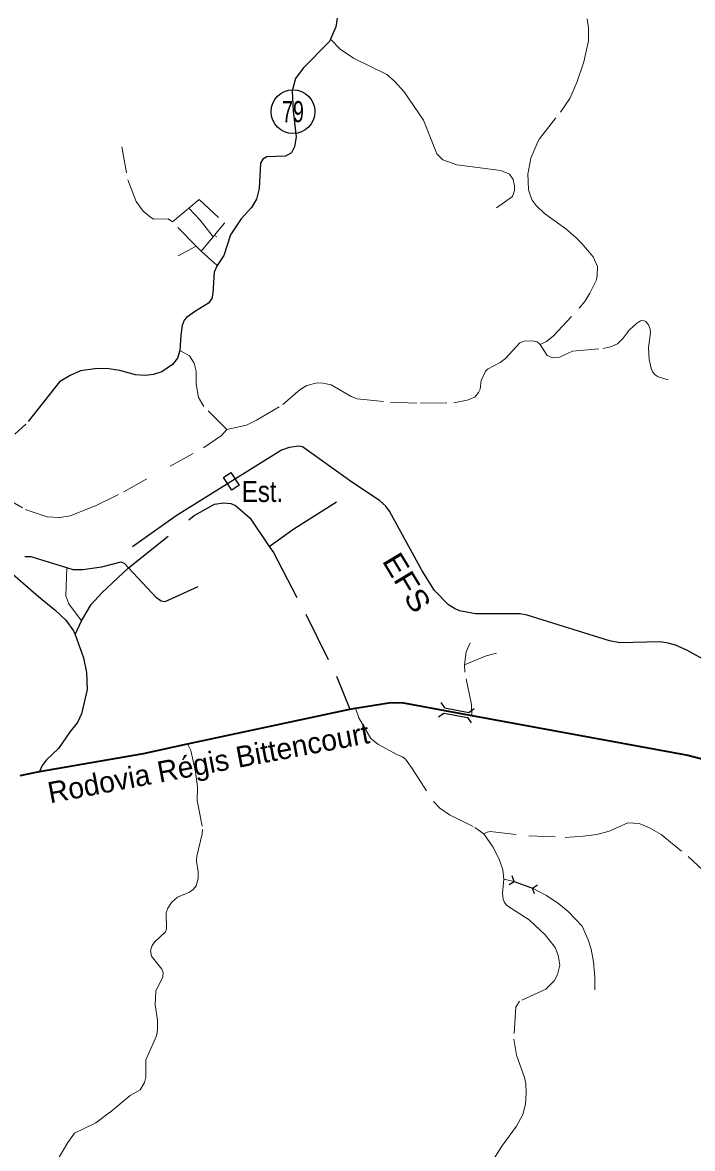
# Model space of a CAD drawing. Extents: x 220.8 to 246.7, y 7287.6 to 7315.8.
# Drawn here: x 232.74 to 235.279, y 7305.147 to 7309.415 of the extents above; entities that cross this region are included whole.
import ezdxf
from ezdxf.enums import TextEntityAlignment as Align

# ---------------------------------------------------------------- set-up
doc = ezdxf.new("R2010")
doc.units = 0
doc.header["$LTSCALE"] = 0.032
for name, pattern in [('DOTTED', [1.5, 0.3, -1.2]), ('LONG_DASHED', [7.5, 6, -1.5]), ('MEDIUM_DASHED', [4.5, 3, -1.5])]:
    doc.linetypes.add(name, pattern=pattern)
for name, color, linetype, lineweight in [('10', 7, 'Continuous', 25), ('13', 7, 'Continuous', 25), ('15', 7, 'Continuous', 25), ('2', 7, 'Continuous', 35), ('28', 7, 'Continuous', 25), ('31', 7, 'Continuous', 25), ('4', 7, 'LONG_DASHED', 25), ('5', 7, 'LONG_DASHED', 13), ('6', 7, 'MEDIUM_DASHED', 13), ('7', 7, 'DOTTED', 13)]:
    doc.layers.add(name, color=color, linetype=linetype, lineweight=lineweight)
doc.layers.add('61', color=7, linetype='Continuous')

msp = doc.modelspace()

# ---------------------------------------------------------------- linework, layer by layer
at = {"layer": '10'}
for p, q in [((234.3399, 7306.8167), (234.3259, 7306.8373)), ((234.3159, 7306.7828), (234.3363, 7306.797)), ((234.3363, 7306.797), (234.4273, 7306.7802)), ((234.4415, 7306.7597), (234.4273, 7306.7802))]:
    msp.add_line(p, q, dxfattribs=at)
msp.add_lwpolyline([(234.3399, 7306.8167), (234.4309, 7306.7998), (234.4515, 7306.814)], dxfattribs=at)
at = {"layer": '13'}
msp.add_circle((233.7647, 7309.0773), 0.083, dxfattribs=at)
at = {"layer": '15'}
msp.add_lwpolyline([(235.3399, 7306.99), (235.2578, 7307.0353), (235.2143, 7307.055), (235.1861, 7307.0627), (235.1561, 7307.0678), (235.0032, 7307.0635), (234.9647, 7307.0712), (234.6528, 7307.1686), (234.6255, 7307.1729), (234.4571, 7307.1737), (234.3964, 7307.1849), (234.3768, 7307.1934), (234.3546, 7307.2079), (234.3016, 7307.2618), (234.2546, 7307.3361), (234.1307, 7307.5626), (234.117, 7307.5814), (234.0931, 7307.6036), (233.9922, 7307.6694), (233.8008, 7307.807), (233.7863, 7307.8095), (233.7504, 7307.8036), (233.7213, 7307.7933), (233.3223, 7307.5455), (233.1573, 7307.4275)], dxfattribs=at)
at = {"layer": '2'}
msp.add_lwpolyline([(232.7314, 7306.5612), (232.8046, 7306.5753), (233.1986, 7306.6434), (233.3657, 7306.6808), (233.9802, 7306.8124), (234.0015, 7306.8162), (234.1355, 7306.8375), (234.184, 7306.8362), (234.3746, 7306.8002), (234.4423, 7306.7876), (235.2612, 7306.6381), (235.937, 7306.461)], dxfattribs=at)
at = {"layer": '28'}
msp.add_lwpolyline([(233.5295, 7307.7089), (233.5609, 7307.6614), (233.5326, 7307.6427), (233.5012, 7307.6902)], close=True, dxfattribs=at)
at = {"layer": '31'}
for p, q in [((234.6027, 7306.1586), (234.5955, 7306.18)), ((234.5836, 7306.1468), (234.6027, 7306.1586)), ((234.6027, 7306.1586), (234.6724, 7306.1338)), ((234.6724, 7306.1338), (234.6917, 7306.1457)), ((234.6798, 7306.1125), (234.6724, 7306.1338))]:
    msp.add_line(p, q, dxfattribs=at)
at = {"layer": '4'}
for points in [[(233.9319, 7309.432), (233.9271, 7309.3981), (233.9071, 7309.3519), (233.9022, 7309.342), (233.8036, 7309.2421), (233.7749, 7309.2022), (233.7612, 7309.156), (233.7662, 7309.0787), (233.7774, 7308.9813), (233.7712, 7308.9439), (233.7599, 7308.9214), (233.7362, 7308.9077), (233.6663, 7308.9052), (233.6501, 7308.8965), (233.6414, 7308.8815), (233.6364, 7308.7854), (233.6264, 7308.7455), (233.6077, 7308.7143), (233.569, 7308.6706), (233.5278, 7308.6107), (233.5029, 7308.5321), (233.4773, 7308.4938), (233.4667, 7308.4684), (233.4617, 7308.3886), (233.4579, 7308.3686), (233.4454, 7308.3511), (233.3955, 7308.3212), (233.3618, 7308.2962), (233.3531, 7308.2862), (233.3456, 7308.2663), (233.3394, 7308.2301), (233.336, 7308.1712), (233.3269, 7308.1427), (233.3082, 7308.119), (233.2682, 7308.0903), (233.2358, 7308.0803), (233.2046, 7308.0766), (233.1684, 7308.0791), (233.1085, 7308.0953), (233.0598, 7308.104), (233.0137, 7308.1028), (232.96, 7308.094), (232.9201, 7308.0766), (232.8801, 7308.0529), (232.7528, 7307.8919), (232.7115, 7307.8548)], [(233.675, 7307.4285), (233.7677, 7307.4962), (233.9853, 7307.6325)], [(233.1415, 7307.3482), (233.3906, 7307.5459), (233.4678, 7307.5888), (233.5012, 7307.5948), (233.5295, 7307.5913), (233.5474, 7307.5836), (233.6023, 7307.5365), (233.675, 7307.4285)], [(232.5207, 7307.5742), (232.5367, 7307.5271), (232.5608, 7307.4793), (232.6023, 7307.4273), (232.6736, 7307.3508), (232.8007, 7307.2393), (232.8629, 7307.1887), (232.9044, 7307.1498), (232.9329, 7307.1096), (232.9391, 7307.0953)], [(233.675, 7307.4285), (233.6906, 7307.4054), (233.8131, 7307.1723), (233.9296, 7306.9375), (233.9802, 7306.8124)], [(233.1415, 7307.3482), (233.1265, 7307.3639), (233.1122, 7307.3696), (233.0398, 7307.3506), (232.9691, 7307.3403), (232.9317, 7307.3403), (232.9085, 7307.3472), (232.7723, 7307.3895), (232.7487, 7307.3895)], [(232.9391, 7307.0953), (232.9633, 7307.1465), (233.0007, 7307.2083), (233.041, 7307.2529), (233.1415, 7307.3482)], [(233.404, 7307.2754), (233.2793, 7307.2188), (233.2655, 7307.2212), (233.2477, 7307.2336), (233.1415, 7307.3482)], [(232.9391, 7307.0953), (232.9706, 7307.0071), (232.9822, 7306.9514), (232.9848, 7306.8865), (232.9641, 7306.7944), (232.9485, 7306.762), (232.92, 7306.727), (232.8759, 7306.6635), (232.8305, 7306.6194), (232.8149, 7306.5986), (232.8046, 7306.5753)]]:
    msp.add_lwpolyline(points, dxfattribs=at)
at = {"layer": '5'}
for points in [[(233.9071, 7309.3519), (233.9432, 7309.3135), (233.9937, 7309.2793), (234.1207, 7309.2174), (234.15, 7309.193), (234.1858, 7309.1523), (234.2591, 7309.0448), (234.3096, 7308.9178), (234.3324, 7308.895), (234.3861, 7308.8755), (234.5522, 7308.8543), (234.5848, 7308.8397), (234.5994, 7308.8201), (234.6043, 7308.7957), (234.6043, 7308.7778), (234.5962, 7308.755), (234.5359, 7308.7126)], [(232.9085, 7307.3472), (232.9039, 7307.2414), (232.915, 7307.2117), (232.9633, 7307.1465)]]:
    msp.add_lwpolyline(points, dxfattribs=at)
at = {"layer": '6'}
for p, q in [((233.4626, 7308.6029), (233.4164, 7308.5479)), ((233.4663, 7308.6073), (233.4626, 7308.6029)), ((233.3303, 7308.53), (233.398, 7308.5667)), ((233.4164, 7308.5479), (233.398, 7308.5667)), ((233.4164, 7308.5479), (233.4773, 7308.4938))]:
    msp.add_line(p, q, dxfattribs=at)
for points in [[(233.3707, 7308.7115), (233.4095, 7308.7442), (233.5038, 7308.6567), (233.5059, 7308.654), (233.4663, 7308.6073), (233.4763, 7308.6044)], [(233.398, 7308.5667), (233.3082, 7308.6588), (233.3707, 7308.7115)], [(233.3707, 7308.7115), (233.4129, 7308.6657), (233.4626, 7308.6029)], [(232.6535, 7307.625), (232.75, 7307.569), (232.8328, 7307.5407), (232.8818, 7307.5384), (232.9201, 7307.5445), (233.0136, 7307.5821), (233.124, 7307.6365), (233.4259, 7307.8027), (233.4941, 7307.8495), (233.514, 7307.8717), (233.4274, 7307.9591), (233.4067, 7307.9935), (233.3975, 7308.0456), (233.3975, 7308.0932), (233.3906, 7308.1238), (233.373, 7308.1514), (233.336, 7308.1712)], [(234.0015, 7306.8162), (234.0145, 7306.779), (234.0597, 7306.701), (234.0864, 7306.6791), (234.1583, 7306.6401), (234.1795, 7306.6319), (234.1911, 7306.6223), (234.2171, 7306.5874), (234.2972, 7306.4615), (234.3218, 7306.4368), (234.3581, 7306.4115), (234.4539, 7306.3636), (234.4882, 7306.3389)], [(233.3657, 7306.6808), (233.378, 7306.6555), (233.396, 7306.575), (233.4032, 7306.5179), (233.4014, 7306.4662), (233.4225, 7306.3562), (233.4212, 7306.3394), (233.4002, 7306.2552), (233.399, 7306.2354), (233.4056, 7306.1957), (233.4056, 7306.1705), (233.3984, 7306.1428), (233.3864, 7306.1284), (233.3732, 7306.1188), (233.3269, 7306.0989), (233.304, 7306.0791), (233.2908, 7306.0574), (233.2848, 7306.0406), (233.286, 7305.9775), (233.2812, 7305.9679), (233.2415, 7305.93), (233.2313, 7305.9162), (233.2247, 7305.8976), (233.2283, 7305.8759), (233.268, 7305.826), (233.2728, 7305.8134), (233.2716, 7305.7978), (233.2451, 7305.7431), (233.2433, 7305.6914), (233.2517, 7305.6337), (233.2511, 7305.5952), (233.2475, 7305.5736), (233.2067, 7305.4828), (233.2067, 7305.4173), (233.2019, 7305.3969), (233.1856, 7305.3692), (233.1478, 7305.3482), (233.0702, 7305.2827), (233.0179, 7305.2442), (232.9374, 7305.2051), (232.9121, 7305.1691), (232.8713, 7305.1011)], [(234.4882, 7306.3389), (234.5012, 7306.3461), (234.5116, 7306.3479), (234.6583, 7306.3318), (234.7965, 7306.326), (234.8649, 7306.3306), (234.9162, 7306.3369), (234.9634, 7306.3496), (235.0336, 7306.3807), (235.0762, 7306.379), (235.1153, 7306.3628), (235.1596, 7306.3364), (235.2626, 7306.2541), (235.376, 7306.1482)], [(234.4882, 7306.3389), (234.5217, 7306.2904), (234.5463, 7306.2438), (234.56, 7306.2034), (234.5641, 7306.1675), (234.5593, 7306.1152), (234.5614, 7306.0919), (234.5662, 7306.0789), (234.5758, 7306.0672), (234.6599, 7306.0139), (234.7208, 7305.9564), (234.7578, 7305.9091), (234.7701, 7305.8797), (234.7763, 7305.8414), (234.7674, 7305.8058), (234.7551, 7305.7825), (234.7236, 7305.7511), (234.623, 7305.7052), (234.6093, 7305.6819), (234.6018, 7305.5615), (234.6113, 7305.5006), (234.6421, 7305.4164), (234.6469, 7305.3931), (234.649, 7305.3575), (234.6456, 7305.3151), (234.6353, 7305.2754), (234.612, 7305.2309), (234.5559, 7305.1556), (234.5285, 7305.1111)]]:
    msp.add_lwpolyline(points, dxfattribs=at)
at = {"layer": '7'}
for points in [[(234.7013, 7308.1943), (234.7251, 7308.2063), (234.7524, 7308.2268), (234.8493, 7308.3317), (234.8704, 7308.3578), (234.8902, 7308.3894), (234.9151, 7308.4397), (234.9176, 7308.4555), (234.9186, 7308.4895), (234.9025, 7308.5264), (234.8599, 7308.5775), (234.8362, 7308.6002), (234.7993, 7308.6329), (234.7184, 7308.6911), (234.6862, 7308.7214), (234.6716, 7308.7417), (234.6645, 7308.7578), (234.6578, 7308.781), (234.6555, 7308.8132), (234.6545, 7308.8397), (234.6659, 7308.9002), (234.6929, 7308.9632), (234.699, 7308.9745), (234.778, 7309.0748), (234.8135, 7309.1264), (234.84, 7309.1875), (234.867, 7309.266), (234.885, 7309.345), (234.8845, 7309.3942), (234.8798, 7309.4293)], [(233.1167, 7308.9439), (233.1388, 7308.8186), (233.1711, 7308.7359), (233.1973, 7308.7001), (233.2249, 7308.6767), (233.2373, 7308.6698), (233.2917, 7308.6712), (233.3082, 7308.6588)], [(234.7013, 7308.1943), (234.7286, 7308.1522), (234.7487, 7308.144), (234.775, 7308.1466), (234.8246, 7308.1693), (234.9397, 7308.1791), (234.9676, 7308.1853), (234.9949, 7308.1972), (235.0156, 7308.2183), (235.0393, 7308.2493), (235.0667, 7308.2741), (235.0822, 7308.2844), (235.0925, 7308.2859), (235.1023, 7308.2818), (235.1121, 7308.2689), (235.1183, 7308.2529), (235.1199, 7308.2405), (235.1116, 7308.1822), (235.1147, 7308.1378), (235.1219, 7308.1042), (235.1276, 7308.0908), (235.1374, 7308.08), (235.1493, 7308.0722), (235.187, 7308.0604)], [(233.514, 7307.8717), (233.5888, 7307.8885), (233.6265, 7307.9071), (233.7261, 7307.9664), (233.7922, 7308.0242), (233.8175, 7308.0387), (233.8562, 7308.0485), (233.8779, 7308.048), (233.9099, 7308.0413), (233.9852, 7307.9969), (234.0079, 7307.9881), (234.1344, 7307.9757), (234.2485, 7307.9716), (234.3739, 7307.9736), (234.4245, 7307.9829), (234.4539, 7307.9953), (234.4684, 7308.0124), (234.4746, 7308.0253), (234.4782, 7308.0583), (234.4942, 7308.0929), (234.502, 7308.1006), (234.55, 7308.1264), (234.5706, 7308.1409), (234.6243, 7308.2008), (234.6413, 7308.2075), (234.6739, 7308.208), (234.6899, 7308.2039), (234.7013, 7308.1943)], [(234.4149, 7306.9804), (234.4206, 7307.03), (234.436, 7307.0633)], [(234.4149, 7306.9804), (234.497, 7307.0146), (234.536, 7307.0243)], [(234.4423, 7306.7876), (234.4409, 7306.8293), (234.4157, 7306.9528), (234.4149, 7306.9804)], [(234.5641, 7306.1675), (234.6027, 7306.1586), (234.6724, 7306.1338), (234.7256, 7306.1062), (234.7718, 7306.074), (234.8073, 7306.0446), (234.861, 7305.9897), (234.8834, 7305.9383), (234.8944, 7305.9023), (234.9034, 7305.8549), (234.9089, 7305.7965), (234.9084, 7305.748)]]:
    msp.add_lwpolyline(points, dxfattribs=at)

# ---------------------------------------------------------------- texts
at = {"layer": '61', "width": 0.7}
msp.add_text('79', height=0.08, dxfattribs=at).set_placement((233.7647, 7309.0372), align=Align.CENTER)
at = {"layer": '61', "width": 0.85}
msp.add_text('Est.', height=0.08, dxfattribs=at).set_placement((233.5712, 7307.5974))
at = {"layer": '61', "width": 1.15}
msp.add_text('EFS', height=0.08, rotation=301.106, dxfattribs=at).set_placement((234.1623, 7307.2717), align=Align.CENTER)
at = {"layer": '61'}
msp.add_text('Rodovia Régis Bittencourt', height=0.08, rotation=10.685, dxfattribs=at).set_placement((233.452, 7306.5695), align=Align.CENTER)

doc.saveas('drawing.dxf')
